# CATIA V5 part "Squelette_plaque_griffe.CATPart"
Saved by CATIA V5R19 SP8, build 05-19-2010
Part number: Squelette plaque griffe
Publications: "Droite.1", "Droite.2", "Droite.3", "Droite.4", "Plan.1", "Plan.4", "Esquisse.2"
Bounding box of the stored display mesh (mm): x -43 to 0, y -26 to 26, z -1.25 to 1.25
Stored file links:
  C:\Users\ThinkMotion\Desktop\EU_thinkMotion\iao\IAO_MMS_Groupe3\ecartoux\projet_IAO_ecartoux\projet_IAO_ecartoux\griffe_d'une_camera_ecartoux\Squelette_plaque_griffe.CATPart
  C:\Users\ThinkMotion\Desktop\EU_thinkMotion\iao\IAO_MMS_Groupe3\ecartoux\projet_IAO_ecartoux\projet_IAO_ecartoux\griffe_d'une_camera_ecartoux\Squelette.CATProduct
  C:\Users\ThinkMotion\Desktop\EU_thinkMotion\iao\IAO_MMS_Groupe3\ecartoux\projet_IAO_ecartoux\projet_IAO_ecartoux\griffe_d'une_camera_ecartoux\Mecanisme_a_coulisse_et_leviers_de_la_griffe_d'un_camera_ecartoux.CATProduct
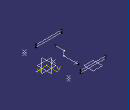
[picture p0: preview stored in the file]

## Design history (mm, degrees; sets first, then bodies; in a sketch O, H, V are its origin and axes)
External parameters (linked from other documents)
  External.a = 5.5 mm
Set1
  Point1: linked copy from another document
  Point2: linked copy from another document
  Plane1: linked copy from another document
  Point3: linked copy from another document
  Point4: linked copy from another document
  Plane2: linked copy from another document
  Plane3 "Plan.3": linked copy from another document
  Point5: linked copy from another document
  Point6: linked copy from another document
Set2 "Set géométrique"
  Line1: type PtDir, RefPoint Point1, Direction Plane1, Start 14, End 43
  Line2: type PtDir, RefPoint Point2, Direction Plane1, Start 14, End 43
  Line3: type PtDir, RefPoint Point3, Direction Plane1, Start 14, End 43
  Line4: type PtDir, RefPoint Point4, Direction Plane1, Start 14, End 43
  Plane4 "Plan.1": type Offset, RefPlane Plane2, Offset 0
  Plane5 "Plan.4": type 2Lines, Element1 Line1, Element2 Line4
  Sketch1 on Plane4, origin (0, 0, 0), H (1, 0, 0), V (0, 1, 0)
    line L1 (-20, 16.795) -> (-20, 0)
    point P1 (-20, 16.795)
    reference projected point E1 (-20, 14) from Point5
    line L2 (-25.5, -5) -> (-25.5, -15.078)
    reference projected point E2 (-20, 14) from Point5
    line L3 (-20, 0) -> (-25.5, -5)
    point P4 (-25.5, -5)
    axis line L4 (-46.2045, 0) -> (9.003, 0)
    point P5 (-46.2045, 0)
    distance L2 L1 = 5.5 {= External.a}
    distance P1 E2 = 2.795
    length L1 = 16.795
    length L2 = 10.078
    distance L4 P4 = 5
    vertical: L1 V, L2 V
    coincidence: L1 E1, P5 H
    horizontal: L4 H
Body1 (main body)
